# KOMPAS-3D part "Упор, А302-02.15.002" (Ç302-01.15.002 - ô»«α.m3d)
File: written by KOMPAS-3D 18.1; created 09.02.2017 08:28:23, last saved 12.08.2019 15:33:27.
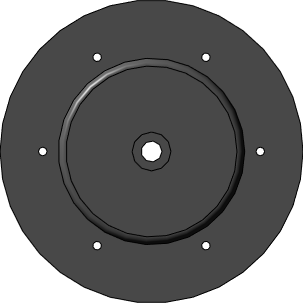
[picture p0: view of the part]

Document properties: Автор: Милов; Организация: Милов; Полное имя файла: D:\Мембранные насосы\Мембранный электропривод\А302-00.00.000 - ASTRA-302 (МЭ200)\3Д ПВХ\А302-01.15.002 - Упор.m3d

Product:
- Part/product: Упор  | designation А302-02.15.002
    Материал: Сталь 12Х18Н10Т ГОСТ 5632-72 (density 7900 kg/m3)
    Масса: 1.60099
    Раздел спецификации: Детали
    Форматы листов документа: A3
    source file: А302-02.00.000 - ASTRA-302 (МЭ200)\А302-02.15.002 - Упор.cdw
- Part/product: Упор  | designation А302-01.15.002
    Масса: 0.395725
    Раздел спецификации: Детали
    Форматы листов документа: A3

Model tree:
1. Эскиз:7
2. Операция вращения:1
     Угол 1 = 360
3. Скругление:18
     Радиус = 6
4. Скругление:19
     Радиус = 2
5. Эскиз:20
6. Вырезать элемент выдавливания:1
     Расстояние 1 = 15
7. Эскиз:21
8. Вырезать элемент выдавливания:2
     Расстояние 1 = 7.5
9. Массив по концентрической сетке:1  (with: Вырезать элемент выдавливания:1, Эскиз:20, Вырезать элемент выдавливания:2, Эскиз:21)  (labels: Сталь 12Х18Н10Т ГОСТ 5632-72)  (6 pattern instances)
     Шаг 2 = 360
10. Массив по концентрической сетке:2  (2 pattern instances)
11. Вырезать элемент выдавливания:1  (with: Эскиз:20)  (4 pattern instances)
     N 1 = 1; Шаг 1 = 10; Шаг 2 = 360; Номер 1 = 1
12. Скругление:20  (with: Операция вращения:1)  (labels: Сталь 12Х18Н10Т ГОСТ 5632-72)
     Радиус = 5

Expressions: 250/2; (250-60)/2; (250-60)/2+12; 13.5/2; 195/2; 25/2

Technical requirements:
  Gost Type A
